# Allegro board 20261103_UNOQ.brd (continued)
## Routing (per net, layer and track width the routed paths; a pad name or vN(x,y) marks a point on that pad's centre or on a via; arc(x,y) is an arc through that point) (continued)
MCU_TRACE_CLK: length 43.6
  S6 w0.064: v1(17.91,9.15) 17.91,9.32 11.86,15.37 11.86,16.32 v5(12.59,17.05)
  G7 w0.064: v5(12.59,17.05) 12.7,17.16 12.7,19.38 14.9,21.58 v1(14.9,21.61)
  BOTTOM w0.066: JMISC1.4 43.81,11.48 41.65,9.31 18.07,9.31 v1(17.91,9.15)
MCU_TRACE_D0: length 69.3
  S6 w0.064: v5(4.67,20.7) 4.22,20.24 4.22,15.51 4.96,14.77 4.96,6.98 6.23,5.71 9.2,5.71 9.47,5.44 12.41,5.44 13.26,4.59 v5(14,4.59)
  G7 w0.064: v5(4.67,20.7) 5.08,20.7 5.21,20.57 6.5,20.57 7.06,20.02 8,20.02 8.26,20.27 9.96,20.27 10.59,20.9 12.47,20.9 13.15,21.58 v1(13.15,21.86) ; v1(20.37,9.57) 20.13,9.33 20.13,6.08 18.8,4.75 14.16,4.75 v5(14,4.59)
  BOTTOM w0.051: MCU1.D3 13.16,22.37 13.16,21.86
  BOTTOM w0.066: JMISC1.6 42.54,10.42 41.58,9.46 20.48,9.46 v1(20.37,9.57) ; 13.16,21.86 v1(13.15,21.86)
MCU_TRACE_D2: length 42.4
  S6 w0.064: v5(12.7,22.38) 12.7,17.47 11.71,16.48 11.71,15.32 17.57,9.46 v1(17.57,9.31)
  G7 w0.064: v1(13.39,22.2) 13.31,22.2 13.13,22.38 v5(12.7,22.38)
  BOTTOM w0.066: JMISC1.8 41.27,10.67 40.28,9.68 21.99,9.68 21.85,9.82 20.29,9.82 19.97,9.5 17.76,9.5 v1(17.57,9.31)
MCU_TRACE_D3: length 66.5
  S6 w0.064: v5(13.87,4.84) 13.23,4.84 12.45,5.62 9.49,5.62 9.26,5.85 6.29,5.85 5.1,7.04 5.1,14.85 4.37,15.58 4.37,19.91 4.95,20.5 4.95,21.56 v5(4.88,21.64)
  G7 w0.064: v1(19.98,9.91) 19.92,9.85 19.92,8.32 19.56,7.96 19.56,6.02 18.51,4.97 14,4.97 v5(13.87,4.84) ; v1(12.9,23.11) 12.69,23.32 12.35,23.32 12.14,23.11 12.14,22.02 11.66,21.54 11.02,21.54 10.9,21.41 8.56,21.41 8.1,20.95 5.36,20.95 4.88,21.44 v5(4.88,21.64)
  BOTTOM w0.066: v1(19.98,9.91) 20.05,9.98 38.69,9.98 40,11.29 40,11.98
MCU_USART1_RX: length 14.2
  S6 w0.064: v5(4.34,20.7) 4.62,20.98 4.62,23.24 4.57,23.29 v5(4.57,23.34)
  G7 w0.064: v1(12.4,23.61) 12.24,23.77 11.13,23.77 10.82,24.08 9.83,24.08 9.5,23.75 7.94,23.75 7.68,23.5 4.72,23.5 v5(4.57,23.34) ; v5(4.34,20.7) 4.62,20.42 6.3,20.42 6.99,19.74 v1(7.01,19.74)
MCU_USART1_RX_CONN: length 66.5
  S3 w0.064: v4(16.84,1.4) 16.84,1.3 17.22,0.92 21.24,0.92 24.02,3.7 24.02,5.76 24.46,6.2 31.27,6.2 32.56,4.9 48.15,4.9 49.6,6.35 50.6,6.35 50.8,6.15 JDIGITAL1.1
  S6 w0.064: v5(8.64,19.46) 8.64,19.09 6.92,17.38 6.92,13.05 6.76,12.88 6.76,10.79 8.9,8.65 11.44,8.65 17.3,2.79 17.3,1.85 v4(16.84,1.4)
  G7 w0.064: v1(7.39,19.23) 7.62,19.46 v5(8.64,19.46)
  BOTTOM w0.064: R2624.2 v1(7.39,19.23)
MCU_USART1_TX: length 3.5
  BOTTOM w0.051: MCU1.B5 14.64,23.37 15.44,23.37
  BOTTOM w0.064: 15.44,23.37 15.8,23.01 15.8,22.81 16.13,22.48 R2623.1
MCU_USART1_TX_CONN: length 62.7
  S3 w0.064: JDIGITAL1.2 49.78,6.6 49.55,6.6 48.03,5.08 32.64,5.08 31.34,6.38 24.39,6.38 23.84,5.83 23.84,3.78 21.16,1.1 17.86,1.1 17.64,1.32 v4(17.37,1.32)
  S6 w0.064: v4(17.37,1.32) 18.01,1.32 18.54,1.85 18.54,5.43 18.29,5.68 18.29,6.9 19.14,7.75 v5(19.14,8.92)
  G7 w0.064: v5(19.14,8.92) 19.14,10.51 18.83,10.82 18.83,12.78 18.49,13.12 18.49,13.79 19.53,14.83 v1(19.53,15.16)
  BOTTOM w0.064: R2623.2 18.31,22.48 19.3,21.49 19.3,15.49 19.53,15.27 v1(19.53,15.16)
MCU_VCAP: length 37
  V5 w0.203: v4(7.09,18.75) 7.39,18.75 8.2,19.56 8.2,25.84 v4(7.35,26.69)
  S6 w0.203: v4(7.35,26.69) 7.37,26.69 7.37,26.7 7.39,26.72 v1(7.62,26.72)
  S6 w0.254: v5(7.37,18.76) 7.1,18.76 v4(7.09,18.75)
  G7 w0.203: v1(19.25,14.99) 19.25,15.01 18.87,15.39 8.1,15.39 7.37,16.12 v5(7.37,18.76)
  BOTTOM w0.051: 8.11,26.61 MCU1.N11
  BOTTOM w0.2: MCU1.A4 15.11,23.11 16.15,22.07 C2501.1 16.31,21.84 16.51,21.64 18.14,21.64 18.92,20.85 18.92,15.37 19.23,15.07 19.23,14.99 v1(19.25,14.99)
  BOTTOM w0.203: v1(7.62,26.72) 8,26.72 8.11,26.61
MCU_VREF+: length 91.1
  V5 w0.524: v4(11.74,51.6) 10.71,52.63 7.93,52.63 7.11,51.81 7.11,50.61 4.8,48.3 4.8,32.79 7.7,29.89 7.7,27.96 6.46,26.72 6.44,26.72 5.58,25.86 5.58,22.23 7.14,20.68 v4(7.57,20.68)
  S6 w0.203: v5(7.87,20.68) v4(7.57,20.68)
  S6 w0.254: v4(11.74,51.6) v1(12.04,51.6)
  G7 w0.203: v1(8.48,20.6) 7.95,20.6 v5(7.87,20.68)
  BOTTOM w0.2: MCU1.L1 9.04,20.76 C2520.1 C2521.1 v1(8.48,20.6)
  BOTTOM w0.254: JDIGITAL1.16 48.44,44.7 48.11,44.37 46.6,44.37 C2614.1 44.39,43.96 44.06,43.63 U2501.3 41.26,43.11 40.57,42.42 34.98,42.42 34.14,41.58 20.22,41.58 18.5,43.3 18.5,47.13 14.39,51.24 12.4,51.24 v1(12.04,51.6)
MCU_VREF_EN: length 133.3
  TOP w0.066: v3(0.93,19.9) 1.04,19.79 1.04,4.45 1.78,3.71 3.62,3.71 v6(4.16,4.25)
  S3 w0.064: v3(0.93,19.9) v4(1.93,19.9)
  S6 w0.064: v5(3.4,19.65) 3.15,19.9 v4(1.93,19.9)
  G7 w0.064: v1(6.11,19.65) 5.9,19.86 3.61,19.86 v5(3.4,19.65) ; v1(48.98,3.82) 47.45,5.35 42.13,5.35 40.39,7.09 24.06,7.09 22.89,5.92 22.89,3.51 21.05,1.67 12.71,1.67 8.96,5.42 5.61,5.42 4.45,4.25 v6(4.16,4.25)
  BOTTOM w0.058: v1(6.11,19.65) 5.87,19.89 5.87,20.31 6.51,20.95 8.04,20.95 8.42,21.33 8.42,21.65 8.64,21.87 9.03,21.87
  BOTTOM w0.066: U2501.6 45.37,44.92 R2515.1 47.56,44.92 48.53,45.89 51.64,45.89 52.02,45.51 52.02,4.45 51.39,3.82 v1(48.98,3.82) ; 9.03,21.87 9.27,22.11 MCU1.M2
MIC2_BIAS: length 47.5
  S3 w0.127: v3(43.85,17.59) 43.6,17.35 42.5,17.35 42.41,17.44 40.71,17.44 v3(40.39,17.11)
  S3 w0.15: v4(20.66,4.35) 20.66,4.26 20.89,4.03 22.27,4.03 22.49,4.26 22.49,6.49 23.7,7.7 45.85,7.7 47.22,9.07 47.22,9.08 47.38,9.24 47.39,9.24 48.13,9.98 48.13,16.71 47.01,17.83 44.08,17.83 v3(43.85,17.59)
  S6 w0.15: v4(20.66,4.35) 20.62,4.31 v1(19.94,4.31)
MIC2_BIAS_CONN: length 6.5
  BOTTOM w0.15: JMISC1.33 24.76,7.55 23.19,5.98 22.14,5.98 21.6,5.44 21.04,5.44 20.61,5.01 D26067.2 20.61,4.88 20.61,4.48 R2646.1
MIC2_INN: length 46.1
  S3 w0.127: v3(39.82,15.98) 41.1,17.26 41.72,17.26 42.21,16.76 42.62,16.76 42.7,16.84 43.6,16.84 v3(43.82,17.06)
  S3 w0.15: v4(21.35,4.41) 21.44,4.32 22.07,4.32 22.24,4.49 22.24,6.59 23.67,8.03 45.62,8.03 47.83,10.24 47.83,16.37 46.83,17.37 44.13,17.37 v3(43.82,17.06)
  S6 w0.15: v1(21.02,4.37) 21.31,4.37 v4(21.35,4.41)
MIC2_INN_CONN: length 6.7
  BOTTOM w0.15: R2637.1 21.5,4.39 D26066.2 22.31,5.72 23.3,5.72 24.62,7.04 25.56,7.04 26.05,7.53 26.05,8.07 JMISC1.31
MIC2_INP: length 44.9
  S3 w0.127: v3(43.82,16.53) 43.52,16.23 42.58,16.23 42.48,16.33 41.25,16.33 40.92,16 40.46,16 40.16,15.7 v3(39.54,15.7)
  S3 w0.15: v4(21.87,4.66) 21.95,4.74 21.95,6.64 23.67,8.36 45.42,8.36 47.57,10.52 47.57,16.27 46.76,17.08 44.37,17.08 v3(43.82,16.53)
  S6 w0.15: v1(22.58,4.37) 22.16,4.37 v4(21.87,4.66)
MIC2_INP_CONN: length 7.5
  BOTTOM w0.15: JMISC1.29 27.32,8.07 27.32,7.64 26.41,6.73 24.71,6.73 23.42,5.44 22.39,5.44 22.09,5.14 D26065.2 22.09,4.38 R2636.1
MIPI_DSI0_CLK_M: length 68.9
  TOP w0.058: U3001.H8 37.53,51.3 37.76,51.3 38.06,51 38.06,50.81 38.3,50.57 38.54,50.57 v3(38.73,50.37)
  S3 w0.051: 29.6,28.33 29.6,28.35 29.59,28.35 29.59,28.48 29.97,28.85 29.97,29.49 v3(30.17,29.68)
  S3 w0.053: 29.6,28.33 29.6,28.14 27.01,25.55 23.25,25.55 21.79,24.09 19.29,24.09 19.16,24.22 18.94,24.22 v4(18.77,24.05) ; v3(38.73,50.37) 38.93,50.56 39.05,50.56 39.25,50.36 39.25,48.85 39.38,48.72 39.38,48.29 v4(39.2,48.11)
  S6 w0.053: v4(39.2,48.11) 39.38,47.93 39.38,45.74 36.27,42.64 34.34,42.64 33.17,41.47 19.5,41.47 18.14,40.1 18.14,32.11 18.26,31.99 19.11,31.99 19.16,31.93 19.16,31.73 19.11,31.68 18.26,31.68 18.14,31.56 18.14,31.19 18.26,31.07 19.1,31.07 19.15,31.02 19.15,30.82 19.1,30.76 18.26,30.76 18.14,30.64 18.14,30.35 18.26,30.22 19.1,30.22 19.15,30.17 19.15,29.97 19.1,29.92 18.26,29.92 18.14,29.8 18.14,29.5 18.26,29.38 18.57,29.38 18.62,29.32 18.62,29.12 18.57,29.07 18.26,29.07 18.14,28.95 18.14,28.65 18.26,28.53 18.57,28.53 18.62,28.47 18.62,28.27 18.57,28.22 18.26,28.22 18.14,28.1 18.14,24.42 18.32,24.24 18.58,24.24 v4(18.77,24.05)
MIPI_DSI0_CLK_M_CONN: length 22
  TOP w0.058: 39.24,50.37 39.44,50.57 40.2,50.57 40.61,50.98 40.94,50.98 41.08,51.12 41.08,51.53 41.14,51.59 41.26,51.59 41.32,51.53 41.32,51.12 41.45,50.98 41.98,50.98 42.13,51.13 42.13,51.5 v3(42.22,51.59)
  S3 w0.053: v4(42.99,53.57) 43.18,53.76 43.18,54.04 43.38,54.24 44.18,54.24 44.5,53.92 44.5,52.61 44.18,52.29 43.53,52.29 43.48,52.24 43.48,52.05 43.36,51.93 43.15,51.93 43.03,52.05 43.03,52.24 42.98,52.29 42.29,52.29 42.11,52.11 42.11,51.7 v3(42.22,51.59)
  S6 w0.053: v4(42.99,53.57) 43.04,53.52 v1(43.04,53.29)
  BOTTOM w0.058: v1(43.04,53.29) 43.14,53.19 43.14,52.91 43.08,52.85 43.07,52.85 43.01,52.79 43.01,52.67 43.07,52.61 43.08,52.61 43.14,52.56 43.14,52.3 43.3,52.15 44.04,52.15 44.16,52.03 44.16,51.59 43.96,51.39 42.18,51.39 42.12,51.45 42.12,51.73 42.3,51.91 U2612.1 U2612.10 42.3,53.24 42.12,53.42 42.12,53.57 42.32,53.77 43.02,53.77 43.25,54 43.25,54.89 43.31,54.95 JMEDIA1.3
MIPI_DSI0_CLK_P: length 68.9
  TOP w0.058: v3(38.73,50.91) 38.54,50.71 38.35,50.71 38.19,50.87 38.19,51.06 37.82,51.43 37.49,51.43 U3001.G8
  S3 w0.051: 29.48,28.33 29.48,28.35 29.48,28.35 29.48,28.52 29.86,28.9 29.86,29.21 29.79,29.28 v3(29.77,29.28)
  S3 w0.053: 29.48,28.33 29.48,28.18 26.96,25.67 23.2,25.67 21.74,24.21 20.87,24.21 20.81,24.26 20.81,24.32 20.76,24.37 20.65,24.37 20.6,24.32 20.6,24.26 20.55,24.21 20.44,24.21 20.39,24.26 20.39,24.32 20.33,24.37 20.23,24.37 20.18,24.32 20.18,24.26 20.12,24.21 20.02,24.21 19.96,24.26 19.96,24.32 19.91,24.37 19.8,24.37 19.75,24.32 19.75,24.26 19.7,24.21 19.34,24.21 19.21,24.34 18.96,24.34 v4(18.77,24.53) ; v4(39.68,48.11) 39.5,48.29 39.5,48.77 39.37,48.9 39.37,50.41 39.1,50.68 38.95,50.68 38.73,50.9 v3(38.73,50.91)
  S6 w0.053: v4(18.77,24.53) 18.6,24.36 18.37,24.36 18.25,24.47 18.25,28.05 18.31,28.1 18.62,28.1 18.74,28.23 18.74,28.52 18.62,28.64 18.31,28.64 18.25,28.7 18.25,28.9 18.31,28.95 18.62,28.95 18.74,29.07 18.74,29.37 18.62,29.49 18.31,29.49 18.25,29.55 18.25,29.75 18.31,29.8 19.15,29.8 19.27,29.92 19.27,30.22 19.15,30.34 18.31,30.34 18.25,30.39 18.25,30.59 18.31,30.65 19.15,30.65 19.27,30.77 19.27,31.07 19.15,31.19 18.31,31.19 18.25,31.24 18.25,31.51 18.31,31.56 19.16,31.56 19.28,31.68 19.28,31.98 19.16,32.1 18.31,32.1 18.25,32.16 18.25,40.05 19.55,41.35 33.22,41.35 34.39,42.52 36.32,42.52 39.5,45.69 39.5,47.93 v4(39.68,48.11)
MIPI_DSI0_CLK_P_CONN: length 22
  TOP w0.058: 39.24,50.91 39.24,50.83 39.36,50.71 39.57,50.71 39.63,50.77 39.63,50.82 39.69,50.88 39.8,50.88 39.86,50.82 39.86,50.77 39.92,50.71 40.15,50.71 40.55,51.11 40.89,51.11 40.95,51.17 40.95,51.58 41.08,51.72 41.31,51.72 41.45,51.58 41.45,51.17 41.51,51.11 41.92,51.11 42,51.19 42,51.48 v3(41.89,51.59)
  S3 w0.053: v4(43.47,53.57) 43.3,53.74 43.3,53.99 43.43,54.12 44.13,54.12 44.38,53.87 44.38,52.66 44.13,52.41 43.48,52.41 43.36,52.29 43.36,52.1 43.31,52.05 43.2,52.05 43.15,52.1 43.15,52.29 43.03,52.41 42.25,52.41 42,52.16 42,51.7 v3(41.89,51.59)
  S6 w0.053: v4(43.47,53.57) 43.37,53.47 v1(43.37,53.29)
  BOTTOM w0.058: JMEDIA1.5 43.05,54.95 43.11,54.89 43.11,54.05 42.96,53.9 42.26,53.9 41.99,53.63 41.99,53.42 41.8,53.23 U2612.9 U2612.2 41.8,51.91 41.98,51.73 41.98,51.39 42.12,51.26 44.02,51.26 44.29,51.53 44.29,52.09 44.1,52.28 43.35,52.28 43.27,52.36 43.27,53.19 v1(43.37,53.29)
MIPI_DSI0_L0_M: length 68.9
  TOP w0.058: 30.17,28.48 v3(30.12,28.35) ; U3001.F8 37.51,52.08 37.9,52.08 38.07,51.91 38.49,51.91 v3(38.71,51.69)
  S3 w0.053: v3(30.12,28.35) 30.04,28.35 30.02,28.33 30.02,28.03 27.24,25.25 23.5,25.25 21.39,23.14 19.53,23.14 v4(19.33,22.94) ; v4(39.94,49.68) 40.12,49.86 40.12,50.91 39.15,51.88 38.9,51.88 v3(38.71,51.69)
  S6 w0.053: v4(19.33,22.94) 19.15,23.11 18.84,23.11 17.63,24.32 17.63,40.27 19.26,41.9 32.95,41.9 34.19,43.14 36.1,43.14 38.69,45.74 38.69,48.46 38.94,48.71 39.89,48.71 40.28,48.32 40.28,47.04 40.33,46.98 40.59,46.98 40.66,47.06 40.66,48.71 40.12,49.25 40.12,49.5 v4(39.94,49.68)
MIPI_DSI0_L0_M_CONN: length 22
  TOP w0.058: R1503.2 39.42,51.89 39.75,51.89 39.99,51.65 40.23,51.65 40.34,51.54 v3(40.35,51.54)
  S3 w0.053: v3(40.35,51.54) 40.47,51.66 40.89,51.66 41.41,51.14 41.41,50.58 41.32,50.49 41.11,50.49 v4(40.92,50.68)
  S6 w0.053: v1(40.65,50.61) 40.85,50.61 v4(40.92,50.68) ; v1(42.3,50.7) 42.49,50.51 42.86,50.51 43.19,50.84 43.19,51.34 43.14,51.39 43.05,51.39 42.99,51.44 42.99,51.55 43.05,51.6 43.14,51.6 43.19,51.66 43.19,51.76 43.14,51.82 43.05,51.82 42.99,51.87 42.99,51.98 43.05,52.03 43.14,52.03 43.19,52.08 43.19,52.39 44.24,53.44 44.24,55.53 44.11,55.66 43.69,55.66 43.64,55.61 43.64,55.4 43.52,55.28 43.32,55.28 43.19,55.4 43.19,55.61 43.14,55.66 43.03,55.66 42.98,55.61 42.98,55.4 42.86,55.28 42.66,55.28 42.53,55.4 42.53,55.61 42.48,55.66 41.76,55.66 41.6,55.82 41.6,56.07 v1(41.48,56.19)
  BOTTOM w0.058: v1(41.48,56.19) 41.59,56.29 41.59,56.77 41.19,57.17 39.79,57.17 39.3,57.66 39.3,58.79 39.24,58.85 JMEDIA1.12 ; v1(40.65,50.61) 40.74,50.52 40.98,50.52 41.16,50.7 U2611.10 v1(42.3,50.7)
MIPI_DSI0_L0_P: length 68.8
  TOP w0.058: SOC1.R30 v3(29.82,28.35) ; U3001.E8 37.51,52.21 37.96,52.21 38.13,52.04 38.53,52.04 v3(38.71,52.22)
  S3 w0.053: v4(19.33,23.41) 19.49,23.26 19.76,23.26 19.81,23.31 19.81,23.37 19.87,23.42 19.97,23.42 20.03,23.37 20.03,23.31 20.08,23.26 21.34,23.26 23.45,25.37 27.2,25.37 29.91,28.08 29.91,28.33 29.89,28.35 v3(29.82,28.35) ; v4(40.41,49.68) 40.23,49.86 40.23,50.95 39.19,51.99 38.94,51.99 v3(38.71,52.22)
  S6 w0.053: v4(19.33,23.41) 19.15,23.23 18.88,23.23 17.74,24.37 17.74,40.22 19.3,41.78 32.99,41.78 34.24,43.03 36.14,43.03 38.81,45.69 38.81,48.41 38.99,48.59 39.84,48.59 40.16,48.27 40.16,46.99 40.28,46.87 40.64,46.87 40.78,47.01 40.78,48.76 40.23,49.3 40.23,49.5 v4(40.41,49.68)
MIPI_DSI0_L0_P_CONN: length 22
  TOP w0.058: R1504.2 39.42,52.02 39.81,52.02 40.05,51.78 40.26,51.78 v3(40.35,51.87)
  S3 w0.053: v4(40.92,50.2) 41.09,50.37 41.37,50.37 41.53,50.53 41.53,51.19 40.94,51.78 40.44,51.78 v3(40.35,51.87)
  S6 w0.053: v1(41.81,56.19) 41.72,56.09 41.72,55.87 41.81,55.78 42.53,55.78 42.65,55.66 42.65,55.45 42.7,55.4 42.81,55.4 42.86,55.45 42.86,55.66 42.99,55.78 43.19,55.78 43.31,55.66 43.31,55.45 43.36,55.4 43.47,55.4 43.52,55.45 43.52,55.66 43.65,55.78 44.16,55.78 44.36,55.58 44.36,53.39 43.31,52.34 43.31,50.79 42.91,50.39 42.49,50.39 v1(42.3,50.2) ; v4(40.92,50.2) 40.84,50.28 v1(40.65,50.28)
  BOTTOM w0.058: v1(40.65,50.28) 40.75,50.38 40.98,50.38 41.16,50.2 U2611.9 v1(42.3,50.2) ; v1(41.81,56.19) 41.72,56.27 41.72,56.83 41.25,57.3 39.85,57.3 39.44,57.71 39.44,58.79 39.5,58.85 JMEDIA1.10
MIPI_DSI0_L1_M: length 68.8
  TOP w0.058: v3(36.91,49.68) 37.1,49.88 37.1,50.24 36.71,50.63 36.71,51.01 U3001.H6
  S3 w0.05: 31.16,28.33 31.16,28.35 v3(31.04,28.47)
  S3 w0.053: v3(36.91,49.68) 36.91,49.46 v4(36.96,49.4) ; 31.16,28.33 31.16,27.8 27.77,24.42 24.47,24.42 20.75,20.7 20.68,20.7 20.67,20.71 20.59,20.71 20.52,20.64 20.52,20.56 20.53,20.55 20.53,20.47 20.45,20.4 20.37,20.4 20.36,20.41 20.29,20.41 20.21,20.33 20.21,20.26 20.22,20.25 20.22,20.17 20.09,20.04 19.74,20.04 19.69,20.09 19.69,20.15 19.63,20.2 19.53,20.2 19.47,20.15 19.47,20.09 19.42,20.04 19.2,20.04 v4(19.02,20.21)
  S6 w0.053: v4(19.02,20.21) 18.83,20.02 18.65,20.02 18.47,20.2 18.47,22.6 16.86,24.21 16.86,40.43 18.98,42.56 32.55,42.56 33.98,43.99 35.76,43.99 37.03,45.26 37.03,48.02 38.07,49.06 38.07,49.69 37.83,49.93 37.26,49.93 37.12,49.79 37.12,49.56 v4(36.96,49.4)
MIPI_DSI0_L1_M_CONN: length 22.3
  TOP w0.058: v3(40.12,48.52) 40.23,48.62 40.23,48.82 40.09,48.96 39.48,48.96 38.8,48.28 37.32,48.28 37.11,48.49 37.11,48.98 R1505.2
  S3 w0.053: v4(41.36,49.18) 41.19,49.01 40.41,49.01 40.23,48.83 40.23,48.63 v3(40.12,48.52)
  S6 w0.053: v1(41.64,49.2) 41.62,49.18 v4(41.36,49.18)
  BOTTOM w0.058: U2611.7 v1(41.64,49.2) U2611.4 42.53,49.2 42.71,49.02 43.13,49.02 44.86,50.75 44.86,51.88 46.24,53.26 46.24,56.34 44.99,57.59 43.37,57.59 43.11,57.85 43.11,58.79 43.05,58.85 JMEDIA1.6
MIPI_DSI0_L1_P: length 68.8
  TOP w0.058: v3(37.44,49.68) 37.24,49.89 37.24,50.29 36.84,50.69 36.84,51.01 U3001.H7
  S3 w0.05: v3(31.04,28.87) 31.16,28.75 31.16,28.74 31.27,28.64 31.27,28.35 31.27,28.35 31.27,28.33
  S3 w0.053: 31.27,28.33 31.27,27.75 27.82,24.3 24.52,24.3 20.14,19.92 19.21,19.92 v4(19.02,19.74) ; v4(37.44,49.4) v3(37.44,49.68)
  S6 w0.053: v4(37.44,49.4) 37.23,49.61 37.23,49.74 37.31,49.81 37.78,49.81 37.96,49.64 37.96,49.11 36.92,48.07 36.92,45.31 35.71,44.11 33.93,44.11 32.5,42.67 18.93,42.67 16.74,40.48 16.74,24.16 18.35,22.55 18.35,20.15 18.6,19.9 18.81,19.9 18.97,19.74 v4(19.02,19.74)
MIPI_DSI0_L1_P_CONN: length 22.3
  TOP w0.058: R1506.2 37.24,48.98 37.24,48.55 37.38,48.41 38.74,48.41 39.42,49.09 40.15,49.09 40.36,48.88 40.36,48.61 v3(40.45,48.52)
  S3 w0.053: v3(40.45,48.52) 40.34,48.63 40.34,48.78 40.46,48.89 41.17,48.89 v4(41.36,48.7)
  S6 w0.053: v4(41.36,48.7) v1(41.64,48.7)
  BOTTOM w0.058: U2611.6 v1(41.64,48.7) U2611.5 42.54,48.7 42.72,48.88 43.18,48.88 44.99,50.69 44.99,51.82 46.37,53.2 46.37,56.4 45.05,57.72 43.43,57.72 43.25,57.9 43.25,58.79 43.31,58.85 JMEDIA1.4
MIPI_DSI0_L2_M: length 68.9
  TOP w0.058: v3(38.71,52.93) 38.51,53.13 38.33,53.13 38.07,52.88 37.51,52.88 U3001.D8
  S3 w0.053: v4(19.22,21.66) 19.41,21.84 20.4,21.84 20.93,22.37 21.2,22.37 23.78,24.95 27.48,24.95 30.43,27.9 30.43,28.74 v3(30.57,28.88) ; v3(38.71,52.93) 38.74,52.96 v4(39.01,52.96)
  S6 w0.053: v4(19.22,21.66) 18.98,21.9 18.8,21.9 18.68,22.03 18.68,22.79 17.18,24.29 17.18,40.4 19.09,42.31 32.65,42.31 33.98,43.64 36,43.64 38.21,45.84 38.21,48.59 38.5,48.88 38.5,50.28 39.22,51 39.4,51 39.52,50.87 39.6,50.87 39.67,50.95 39.67,51.02 39.55,51.15 39.55,51.32 39.8,51.58 39.8,52.9 39.55,53.15 39.2,53.15 v4(39.01,52.96)
MIPI_DSI0_L2_M_CONN: length 22.3
  TOP w0.058: R1507.2 39.4,53.12 39.5,53.12 v3(39.6,53.02)
  S3 w0.053: v3(39.6,53.02) 39.71,53.13 40,53.13 40.14,53.27 40.14,53.55 40.19,53.6 40.24,53.6 40.29,53.65 40.29,53.76 40.24,53.81 40.19,53.81 40.14,53.86 40.14,54.99 40.02,55.12 39.01,55.12 38.96,55.17 38.96,55.28 39.01,55.33 40.02,55.33 40.14,55.45 40.14,55.65 40.02,55.78 39.01,55.78 38.96,55.83 38.96,55.94 39.01,55.99 40.02,55.99 40.14,56.11 40.14,56.84 40.26,56.96 40.63,56.96 40.74,56.85 40.74,55.05 40.99,54.8 41.24,54.8 v4(41.41,54.63)
  S6 w0.053: v4(41.41,54.63) 41.23,54.81 40.66,54.81 40.53,54.68 40.53,53.9 40.58,53.85 41.29,53.85 41.41,53.72 41.41,53.52 41.29,53.4 40.58,53.4 40.53,53.35 40.53,52.46 40.6,52.39 40.6,52.16 v1(40.71,52.05)
  BOTTOM w0.058: v1(40.71,52.05) U2612.4 U2612.7 40.62,53.2 40.62,53.6 40.42,53.8 39.68,53.8 39.44,54.04 39.44,54.89 39.5,54.95 JMEDIA1.9
MIPI_DSI0_L2_P: length 68.9
  TOP w0.058: v3(38.71,53.44) 38.53,53.26 38.27,53.26 38.02,53.01 37.51,53.01 U3001.C8
  S3 w0.053: v4(39.01,53.44) v3(38.71,53.44) ; v3(30.17,28.88) 30.31,28.74 30.31,27.95 27.43,25.07 23.73,25.07 21.16,22.49 20.88,22.49 20.35,21.96 20.02,21.96 19.97,22.01 19.97,22.11 19.92,22.16 19.81,22.16 19.76,22.11 19.76,22.01 19.7,21.96 19.4,21.96 v4(19.22,22.14)
  S6 w0.053: v4(39.01,53.44) 39.19,53.26 39.6,53.26 39.92,52.95 39.92,51.53 39.66,51.27 39.66,51.2 39.79,51.07 39.79,50.9 39.65,50.76 39.47,50.76 39.35,50.88 39.27,50.88 38.62,50.23 38.62,48.83 38.33,48.54 38.33,45.8 36.05,43.52 34.03,43.52 32.7,42.19 19.13,42.19 17.3,40.35 17.3,24.34 18.8,22.84 18.8,22.07 18.85,22.02 19.11,22.02 v4(19.22,22.14)
MIPI_DSI0_L2_P_CONN: length 22.3
  TOP w0.058: v3(39.6,53.35) 39.5,53.25 39.4,53.25 R1508.2
  S3 w0.053: v4(41.41,55.11) 41.22,54.92 41.04,54.92 40.86,55.1 40.86,56.9 40.68,57.08 40.21,57.08 40.02,56.89 40.02,56.16 39.97,56.11 38.96,56.11 38.84,55.98 38.84,55.78 38.96,55.66 39.97,55.66 40.02,55.61 40.02,55.5 39.97,55.45 38.96,55.45 38.84,55.32 38.84,55.12 38.96,55 39.97,55 40.02,54.95 40.02,53.32 39.95,53.24 39.71,53.24 v3(39.6,53.35)
  S6 w0.053: v4(41.41,55.11) 41.23,54.93 40.61,54.93 40.41,54.73 40.41,53.85 40.53,53.73 41.24,53.73 41.3,53.68 41.3,53.57 41.24,53.52 40.53,53.52 40.41,53.39 40.41,52.41 40.48,52.34 40.48,52.15 v1(40.38,52.05)
  BOTTOM w0.058: v1(40.38,52.05) 40.3,52.13 U2612.5 U2612.6 40.49,53.2 40.49,53.54 40.36,53.67 39.62,53.67 39.3,53.99 39.3,54.89 39.24,54.95 JMEDIA1.11
MIPI_DSI0_L3_M: length 68.9
  TOP w0.058: U3001.H4 35.91,51.01 35.91,49.88 v3(35.71,49.68)
  S3 w0.05: 30.64,28.33 30.64,28.39 30.65,28.4 ; v3(30.57,29.28) 30.64,29.21
  S3 w0.053: 30.64,29.21 30.64,29.06 30.74,28.96 30.74,28.81 30.65,28.71 30.65,28.4 ; v3(35.71,49.68) 35.71,49.43 v4(35.74,49.4) ; v4(17.83,21.44) 17.83,21.21 17.93,21.11 18.12,21.11 18.18,21.16 18.18,21.21 18.23,21.26 18.34,21.26 18.39,21.21 18.39,21.16 18.44,21.11 18.55,21.11 18.6,21.16 18.6,21.21 18.66,21.26 18.76,21.26 18.82,21.21 18.82,21.16 18.87,21.11 18.98,21.11 19.03,21.16 19.03,21.21 19.08,21.26 19.19,21.26 19.24,21.21 19.24,21.16 19.3,21.11 19.4,21.11 19.46,21.16 19.46,21.21 19.51,21.26 19.62,21.26 19.67,21.21 19.67,21.16 19.72,21.11 19.83,21.11 19.88,21.16 19.88,21.21 19.94,21.26 20.04,21.26 20.1,21.21 20.1,21.16 20.15,21.11 20.37,21.11 20.5,21.24 20.5,21.32 20.48,21.34 20.48,21.41 20.56,21.49 20.63,21.49 20.66,21.47 20.73,21.47 20.81,21.54 20.81,21.62 20.78,21.64 20.78,21.71 20.86,21.79 20.94,21.79 20.96,21.77 21.03,21.77 24.03,24.77 27.65,24.77 30.64,27.76 30.64,28.33
  S6 w0.053: v4(35.74,49.4) 35.92,49.58 35.92,49.67 35.87,49.72 35.42,49.72 35.23,49.53 35.23,49.18 35.85,48.55 35.85,48.38 35.72,48.25 35.72,48.17 35.8,48.1 35.87,48.1 36,48.23 36.18,48.23 36.63,47.78 36.63,45.57 35.59,44.53 33.94,44.53 32.38,42.96 18.81,42.96 16.45,40.6 16.45,23.8 17.42,22.82 17.42,21.59 17.58,21.44 v4(17.83,21.44)
MIPI_DSI0_L3_M_CONN: length 22.2
  TOP w0.058: R1509.2 35.9,48.99 35.9,48.71 35.84,48.65 35.66,48.65 35.6,48.59 35.6,48.47 35.66,48.41 35.84,48.41 35.9,48.36 35.9,47.91 35.19,47.2 31.42,47.2 31.33,47.29 31.33,47.61 31.43,47.71 34.4,47.71 34.61,47.92 34.61,48.37 34.41,48.57 33.55,48.57 v3(33.44,48.68)
  S3 w0.053: v4(33.15,48.77) 33.24,48.68 v3(33.44,48.68)
  S6 w0.053: v1(32.87,48.69) 33.07,48.69 v4(33.15,48.77)
  BOTTOM w0.058: JMEDIA1.15 35.69,54.95 35.63,54.89 35.63,53.88 35.49,53.74 34.56,53.74 34.44,53.62 34.44,53.31 U2606.10 U2606.1 34.63,52.01 34.45,51.83 34.45,51.6 32.41,49.57 32.41,48.67 32.48,48.6 32.78,48.6 v1(32.87,48.69)
MIPI_DSI0_L3_P: length 68.9
  TOP w0.058: U3001.H5 36.04,51.01 36.04,49.86 v3(36.22,49.68)
  S3 w0.05: 30.76,28.4 30.76,28.38 30.76,28.38 30.76,28.35 30.76,28.34 30.76,28.33 ; 30.76,29.21 30.76,29.22 30.76,29.22 30.76,29.25 ; 30.76,29.49 v3(30.57,29.68)
  S3 w0.053: 30.76,29.25 30.76,29.49 ; v4(36.22,49.4) v3(36.22,49.68) ; v4(17.49,21.1) 17.77,21.1 17.88,20.99 20.42,20.99 24.08,24.65 27.7,24.65 30.76,27.71 30.76,28.33 ; 30.76,28.4 30.76,28.66 30.86,28.76 30.86,29 30.76,29.1 30.76,29.21
  S6 w0.053: v4(36.22,49.4) 36.04,49.58 36.04,49.72 35.92,49.84 35.37,49.84 35.11,49.58 35.11,49.13 35.74,48.5 35.74,48.43 35.61,48.3 35.61,48.12 35.75,47.98 35.92,47.98 36.05,48.11 36.13,48.11 36.51,47.73 36.51,45.62 35.54,44.64 33.89,44.64 32.33,43.08 18.77,43.08 16.33,40.65 16.33,23.75 17.31,22.77 17.31,21.54 17.49,21.36 v4(17.49,21.1)
MIPI_DSI0_L3_P_CONN: length 22.1
  TOP w0.058: v3(33.44,48.35) 33.53,48.44 34.35,48.44 34.48,48.31 34.48,47.98 34.34,47.84 31.37,47.84 31.2,47.67 31.2,47.23 31.36,47.07 35.25,47.07 36.03,47.85 36.03,48.99 R1510.2
  S3 w0.053: v3(33.44,48.35) 33.21,48.35 v4(33.15,48.29)
  S6 w0.053: v4(33.15,48.29) 33.08,48.36 v1(32.87,48.36)
  BOTTOM w0.058: 34.92,54.95 35.43,54.95 35.49,54.89 35.49,53.93 35.43,53.87 34.5,53.87 34.31,53.68 34.31,53.29 U2606.9 U2606.2 34.13,52.01 34.31,51.83 34.31,51.66 32.28,49.62 32.28,48.61 32.42,48.47 32.76,48.47 v1(32.87,48.36)
MUX_ALERT: length 51
  TOP w0.066: U3001.B8 37.54,53.54 v3(37.64,53.44) 38.25,54.05 R3025.2 ; v3(25.32,28.55) 24.99,28.88 SOC1.AG29
  S3 w0.064: v4(39.41,43.62) 39.41,46.13 38.5,47.04 38.5,50 38.28,50.22 38.28,51.88 37.64,52.52 v3(37.64,53.44) ; v3(25.32,28.55) 25.03,28.26 20.22,28.26 20.17,28.21 v4(19.53,28.21)
  S6 w0.064: v4(39.41,43.62) 38.72,42.94 37.34,42.94 36.52,42.11 34.51,42.11 33.19,40.79 22.12,40.79 19.5,38.17 19.5,37.13 19.86,36.77 19.86,28.91 19.53,28.57 v4(19.53,28.21)
MUX_CABLE_DET: length 42.3
  TOP w0.066: v3(14.89,49.25) 22.01,49.25 v3(22.55,49.79) ; v3(33.83,51.66) 33.43,52.07 TP3007.1 ; SOC1.AG1 v3(24.54,40.51)
  S3 w0.064: v3(35.37,53.14) 35.37,53.1 35.15,52.88 34.52,52.88 34.44,52.81 34.44,52.27 v3(33.83,51.66) 33.71,51.54 33.71,51.05 34.37,50.39 34.37,50.08 34.21,49.92 32.96,49.92 32.17,50.71 30.7,50.71 30.5,50.91 v4(30.09,50.91) ; v3(22.55,49.79) 22.55,50.14 v4(22.47,50.22) ; v3(24.54,40.51) 24.43,40.61 22.56,40.61 20.47,42.7 18.59,42.7 15.83,45.46 15.83,48.37 14.95,49.25 v3(14.89,49.25)
  S6 w0.064: v4(30.09,50.91) 29.93,51.07 26.52,51.07 26.34,50.89 26.34,50.3 26.26,50.22 v4(22.47,50.22)
MUX_DP_HPD: length 4.9
  TOP w0.066: SOC1.K1 31.77,41.45 32.18,41.86 34.99,41.86 R3028.2
MUX_DP_HPD_R: length 15.5
  TOP w0.066: v3(39.25,41.73) 39.1,41.88 35.77,41.88 R3028.1
  S3 w0.064: v3(39.25,41.73) 39.03,41.95 38.71,41.95 38.51,42.15 38.51,46.21 37.97,46.75 37.97,49.86 37.82,50.01 37.82,51.52 37.02,52.32 v3(36.98,52.32)
MUX_I2C_SCL_R: length 14
  TOP w0.066: R3014.2 35.51,43.78 TP3002.1 35.89,43.82 36.17,44.1 37.97,44.1 38.35,43.72 v3(38.8,43.72)
  S3 w0.064: v3(38.8,43.72) 38.8,46.23 38.15,46.88 38.15,49.9 37.97,50.08 37.97,51.63 37.02,52.58 37.02,52.74 v3(36.98,52.78)
MUX_I2C_SDA_R: length 19.2
  TOP w0.066: R3015.2 30.99,44.43 TP3003.1 31.35,44.79 37.53,44.79 38.39,43.93 v3(39.01,43.93)
  S3 w0.064: v3(37.01,53.11) 37.2,52.92 37.2,52.69 38.13,51.76 38.13,50.13 38.32,49.94 38.32,46.96 38.98,46.3 38.98,44.51 39.01,44.48 v3(39.01,43.93)
MUX_LDO_EN: length 1.1
  TOP w0.066: 25.7,60.83 25.7,60.82 U3004.3
MUX_POWER_EN: length 55.1
  TOP w0.066: SOC1.AE1 25.77,40.45 25.58,40.64 v3(25.5,40.64)
  G2 w0.191: v3(34.77,52.58) 34.8,52.58 v2(34.95,52.73)
  S3 w0.064: v4(35.05,52.53) 34.98,52.53 34.92,52.58 v3(34.77,52.58) ; v4(15.03,51.54) 14.37,50.88 14.37,50.16 16.03,48.5 16.03,45.49 18.64,42.88 20.56,42.88 22.68,40.76 25.39,40.76 v3(25.5,40.64)
  S6 w0.064: v1(15.3,51.42) 15.15,51.42 v4(15.03,51.54) ; v1(35.26,52.73) v4(35.05,52.53)
  BOTTOM w0.066: TP3001.1 16.01,50.74 15.99,50.74 ; 15.99,50.74 19.37,47.36 19.37,43.43 20.43,42.36 30.3,42.36 32.76,44.82 32.76,47.47 33.44,48.15 33.44,49.98 35.59,52.13 R3022.2 35.59,52.68 C3028.1 35.43,52.91 v1(35.26,52.73) ; 15.99,50.74 v1(15.3,51.42)
MUX_RESET_N: length 43.1
  TOP w0.066: v3(38.71,54.43) R3023.2 38.53,54.79 TP3006.1 38.68,55.32 C3027.1
  S3 w0.064: 37.97,53.49 37.97,52.49 38.43,52.02 38.43,50.28 38.66,50.06 38.66,47.2 v4(40.08,45.78) ; 37.97,53.49 37.97,53.71 38.08,53.82 38.38,53.82 38.71,54.15 v3(38.71,54.43) ; 37.97,53.49 37.8,53.66 37.09,53.66 v3(37.02,53.59) ; v4(19.24,38.33) 19.77,38.33 19.92,38.48 v3(25.37,38.48)
  S6 w0.064: v4(19.24,38.33) 19.46,38.33 22.15,41.02 33.22,41.02 34.49,42.29 36.5,42.29 39.99,45.78 v4(40.08,45.78)
MUX_SBU1: length 4.9
  TOP w0.051: v3(35.73,59.77) U2602.1 35.73,58.61 35.88,58.46 35.88,58.19 C3019.2 34.93,58.01 R3003.2
  S3 w0.048: v3(35.73,59.77) 35.9,59.94 35.9,60.26 36.18,60.53 36.59,60.53 37.03,60.98 37.03,61.17 v3(36.97,61.23)
MUX_SBU2: length 8.2
  TOP w0.051: R3004.2 C3020.2 36.06,58.19 36.06,58.45 36.23,58.62 U2602.2 v3(36.23,59.77)
  S3 w0.048: v3(38.72,62.53) 38.33,62.92 37.27,62.92 36.97,62.62 36.97,61.59 37.19,61.37 37.19,60.91 36.66,60.38 36.25,60.38 36.06,60.19 36.06,59.94 v3(36.23,59.77)
MUX_SSRXN1: length 20.1
  TOP w0.053: C2629.2 R2665.1 44.21,61.11 43.92,60.82 43.92,59.82 44.08,59.66 44.08,58.87 v3(44.2,58.75)
  S3 w0.051: v3(44.2,58.75) 44.26,58.81 v4(44.26,59.03) ; v3(35.37,53.54) 35.51,53.68 35.51,53.87 35.13,54.25 35.13,55.38 35.08,55.43 34.97,55.43 34.92,55.48 34.92,55.58 34.97,55.63 35.08,55.63 35.13,55.68 35.13,55.86 v4(34.95,56.03)
  S6 w0.051: v4(34.95,56.03) 35.13,56.21 35.13,56.54 35.41,56.82 37.23,56.82 37.74,56.31 40.03,56.31 41.73,58.02 44.29,58.02 44.7,58.42 44.7,59.41 44.55,59.56 44.22,59.56 44.08,59.42 44.08,59.2 v4(44.26,59.03)
MUX_SSRXN1_C: length 7.4
  TOP w0.053: D26102.2 44.16,62.77 ; 44.16,62.77 43.92,63.01 43.92,63.54 43.52,63.94 42.19,63.94 42.06,64.07 40.35,64.07 39.9,63.62 39.9,63.04 39.72,62.86 JUSB1.B10 ; 44.16,62.77 44.13,62.77 43.92,62.56 43.92,62.47 44.18,62.21 44.25,62.21 C2629.1
MUX_SSRXN2: length 6.6
  TOP w0.053: C2627.1 32.44,58.47 32.94,58.47 33.24,58.17 33.24,57.57 R2660.1 33.25,57.14 33.25,56.13 34.35,55.03 34.63,55.03 35.24,54.41 35.24,54.07 U3001.A3
MUX_SSRXN2_C: length 10.3
  TOP w0.053: JUSB1.A10 35.97,60.86 35.79,60.68 35.79,60.53 35.16,59.9 32.59,59.9 32.34,59.64 31.83,59.64 31.64,59.45 U2601.6 U2601.5 30.27,59.45 30.09,59.63 29.93,59.63 29.87,59.57 29.87,58.73 30.13,58.47 30.76,58.47 30.81,58.52 30.81,58.57 30.87,58.62 30.97,58.62 31.03,58.57 31.03,58.52 31.08,58.47 31.56,58.47 C2627.2
MUX_SSRXP1: length 20.3
  TOP w0.053: C2630.2 R2664.1 43.46,61.11 43.78,60.8 43.78,59.76 43.94,59.6 43.94,58.87 v3(43.82,58.75)
  S3 w0.051: v4(43.78,59.03) 43.76,59.01 43.76,58.81 v3(43.82,58.75) ; v4(35.43,56.03) 35.25,55.85 35.25,54.3 35.63,53.92 35.63,53.69 v3(35.77,53.54)
  S6 w0.051: v4(35.43,56.03) 35.25,56.21 35.25,56.49 35.46,56.7 37.18,56.7 37.69,56.19 40.08,56.19 41.78,57.89 44.35,57.89 44.82,58.37 44.82,59.46 44.6,59.68 44.17,59.68 43.96,59.47 43.96,59.21 v4(43.78,59.03)
MUX_SSRXP1_C: length 7.3
  TOP w0.053: C2630.1 43.51,62.21 43.78,62.48 43.78,62.59 43.58,62.79 43.54,62.79 ; 43.54,62.79 43.78,63.03 43.78,63.48 43.46,63.8 42.13,63.8 42.01,63.93 41.4,63.93 41.34,63.88 41.34,63.83 41.29,63.78 41.18,63.78 41.13,63.83 41.13,63.88 41.08,63.93 40.97,63.93 40.92,63.88 40.92,63.83 40.86,63.78 40.76,63.78 40.7,63.83 40.7,63.88 40.65,63.93 40.41,63.93 40.04,63.56 40.04,63.03 40.22,62.85 JUSB1.B11 ; 43.54,62.79 D26103.2
MUX_SSRXP2: length 6.6
  TOP w0.053: U3001.A2 35.1,54.07 35.1,54.36 34.98,54.48 34.9,54.48 34.87,54.46 34.8,54.46 34.72,54.53 34.72,54.61 34.75,54.63 34.75,54.71 34.57,54.89 34.29,54.89 33.11,56.07 33.11,57.1 R2661.1 33.1,57.59 33.1,58.11 32.88,58.34 32.44,58.34 C2628.1
MUX_SSRXP2_C: length 10.4
  TOP w0.053: C2628.2 31.57,58.33 30.07,58.33 29.73,58.67 29.73,59.63 29.87,59.77 30.07,59.77 30.25,59.95 U2601.4 U2601.7 31.64,59.95 31.81,59.78 32.28,59.78 32.53,60.03 35.1,60.03 35.65,60.59 35.65,60.69 35.47,60.87 JUSB1.A11
MUX_SSTXN1: length 11.5
  TOP w0.053: v3(36.21,54.57) 36.3,54.48 36.3,54.07 U3001.A5
  S3 w0.051: v3(42.46,57.69) 42.67,57.48 42.67,56.97 42.85,56.79 43.19,56.79 v4(43.38,56.6) ; v3(36.21,54.57) 36.21,54.8 v4(36.15,54.86)
  S6 w0.051: v4(36.15,54.86) 36.32,54.69 36.32,54.36 36.46,54.23 37.87,54.23 39.3,55.65 40.24,55.65 41.37,56.78 43.2,56.78 v4(43.38,56.6)
MUX_SSTXN1_C: length 6.1
  TOP w0.053: C2602.1 42.64,58.38 42.64,58.95 D26105.2 42.65,59.32 42.65,60.14 42.49,60.3 39.83,60.3 39.65,60.48 39.65,60.68 39.47,60.86 JUSB1.A3
MUX_SSTXN2: length 19.7
  S3 w0.051: v3(36.57,53.54) 36.44,53.68 36.44,53.73 36.65,53.94 37.62,53.94 38.46,54.78 38.46,57.77 v4(38.63,57.94) ; v4(28.92,57.05) 29.11,57.24 29.11,58.61 28.87,58.85 28.87,59.4 v3(28.65,59.62)
  S6 w0.051: v4(28.92,57.05) 29.11,57.23 29.11,57.37 29.33,57.59 32.05,57.59 32.44,57.98 35.84,57.98 36.56,58.7 38.1,58.7 38.45,58.35 38.45,58.12 v4(38.63,57.94)
MUX_SSTXN2_C: length 11.8
  TOP w0.053: C2603.1 28.89,60.36 28.89,60.94 29.22,61.27 30.07,61.27 30.25,61.45 U2601.1 U2601.10 31.64,61.45 31.82,61.27 32.06,61.27 32.2,61.41 32.2,63 33.22,64.01 35.69,64.01 36.04,63.66 36.04,63.07 36.22,62.89 JUSB1.B3
MUX_SSTXP1: length 11.4
  TOP w0.053: U3001.A6 36.44,54.07 36.44,54.48 v3(36.54,54.57)
  S3 w0.051: v3(42.99,57.69) 42.79,57.48 42.79,57.02 42.9,56.91 43.21,56.91 v4(43.38,57.08) ; v4(36.63,54.86) 36.54,54.77 v3(36.54,54.57)
  S6 w0.051: v4(36.63,54.86) 36.45,54.68 36.45,54.41 36.51,54.35 36.76,54.35 36.81,54.4 36.81,54.43 36.87,54.48 36.97,54.48 37.02,54.43 37.02,54.4 37.07,54.35 37.17,54.35 37.22,54.4 37.22,54.43 37.27,54.48 37.37,54.48 37.42,54.43 37.42,54.4 37.48,54.35 37.82,54.35 39.25,55.77 40.19,55.77 41.32,56.9 43.2,56.9 v4(43.38,57.08)
MUX_SSTXP1_C: length 6.1
  TOP w0.053: C2601.1 42.78,58.41 42.78,58.95 D26104.2 42.79,59.3 42.79,60.2 42.55,60.44 39.89,60.44 39.79,60.53 39.79,60.67 39.97,60.85 JUSB1.A2
MUX_SSTXP2: length 19.6
  S3 w0.051: v3(29.2,59.62) 28.99,59.41 28.99,58.9 29.23,58.66 29.23,57.22 v4(29.4,57.05) ; v4(38.15,57.94) 38.33,57.76 38.33,54.83 37.93,54.42 37.85,54.42 37.82,54.45 37.75,54.45 37.68,54.38 37.68,54.3 37.71,54.27 37.71,54.2 37.57,54.07 37.26,54.07 37.21,54.12 37.21,54.15 37.16,54.2 37.06,54.2 37.01,54.15 37.01,54.12 36.96,54.07 36.6,54.07 36.32,53.78 36.32,53.69 v3(36.17,53.54)
  S6 w0.051: v4(38.15,57.94) 38.33,58.11 38.33,58.3 38.05,58.58 36.61,58.58 35.89,57.86 32.49,57.86 32.1,57.47 29.38,57.47 29.23,57.32 29.23,57.22 v4(29.4,57.05)
MUX_SSTXP2_C: length 11.7
  TOP w0.053: JUSB1.B2 35.72,62.9 35.9,63.08 35.9,63.6 35.63,63.87 35.45,63.87 35.4,63.82 35.4,63.77 35.34,63.72 35.24,63.72 35.18,63.77 35.18,63.82 35.13,63.87 35.02,63.87 34.97,63.82 34.97,63.77 34.92,63.72 34.81,63.72 34.76,63.77 34.76,63.82 34.7,63.87 33.27,63.87 32.34,62.94 32.34,61.35 32.12,61.13 31.8,61.13 31.62,60.95 U2601.9 U2601.2 30.25,60.95 30.07,61.13 29.28,61.13 29.03,60.88 29.03,60.29 C2604.1
MUX_XTAL_IN: length 6.4
  TOP w0.066: Y3001.1 29.05,52.93 29.87,53.75 31.94,53.75 32.19,53.49 C3021.1 32.56,53.54 R3007.2 33.39,53.54 34.19,52.74 34.57,52.74 U3001.D1
MUX_XTAL_OUT: length 4
  TOP w0.066: Y3001.3 31.6,54.08 C3022.1 32.54,54.05 R3007.1 33.17,54.05 34.08,53.14 34.57,53.14 U3001.C1
OSC_16M_IN: length 4.1
  BOTTOM w0.066: Y2501.1 10.39,17.41 10.39,18.89 C2522.1 10.62,19.21 10.62,19.79 R2509.2
OSC_16M_OUT: length 2.1
  BOTTOM w0.066: R2511.2 10.06,19.81 C2523.1 10.06,18.84 Y2501.3
OSC_32K_IN: length 4.7
  BOTTOM w0.066: R2514.1 14.07,19.15 C2528.1 R2512.2 15.67,18.54 16.36,17.85 Y2502.2
OSC_32K_OUT: length 2.8
  BOTTOM w0.066: R2513.2 13.49,19.15 C2527.1 13.51,18.57 R2512.1 13.56,18.52 Y2502.1
PACK_VSNS_M: length 7.8
  TOP w0.066: v3(46.28,16.84) 46.29,16.85 R604.1
  S3 w0.064: v3(46.28,16.84) 46.28,16.74 46.35,16.67 46.58,16.67 46.76,16.49 46.76,16.15 46.61,16 45.2,16 43.87,14.67 40.78,14.67 v3(40.68,14.58)
PHONE_ON_N: length 78.3
  TOP w0.066: JBTN1.1 47.15,58.17 47.52,57.8 D26009.2 47.54,57.17 C2605.1 48.05,56.88 v3(48.84,56.08) ; JBTN1.1 47.2,58.54 48.39,59.73 49.94,59.73 v6(50.11,59.9) ; JBTN1.1 JBTN1.2
  S3 w0.064: v3(48.84,56.08) 48.84,55.04 48.71,54.9 48.71,51.71 49.24,51.18 49.24,21.6 48.44,20.8 48.44,9.71 v4(47.47,8.74) ; v4(38.58,14.74) 38.19,15.13 v3(37.28,15.13)
  S6 w0.064: v4(38.58,14.74) 38.58,14.22 40.82,11.98 40.82,11.02 41.97,9.87 43.01,9.87 43.54,9.35 46.86,9.35 v4(47.47,8.74)
  BOTTOM w0.066: TP2614.1 49.37,59.83 49.44,59.9 v6(50.11,59.9)
PM_AVDD_BYP: length 4.7
  S3 w0.064: v3(35.58,16.26) 35.48,16.36 35.24,16.36 34.89,16.01 34.6,16.01 33.54,14.95 33.04,14.95 32.77,14.68 32.76,14.68 32.74,14.66 32.1,14.66 31.8,14.96 31.8,14.95 v3(31.78,14.95)
PM_DVDD_BYP: length 5
  S3 w0.064: v3(35.86,15.98) 35.6,15.98 35.51,16.07 35.51,16.07 35.4,16.18 35.23,16.18 34.92,15.87 34.79,15.87 33.63,14.71 33.63,14.52 33.43,14.32 33.1,14.32 33.04,14.38 32.74,14.38 32.62,14.5 v3(31.85,14.5)
PM_REF_BYP: length 5.3
  TOP w0.066: C716.1 v3(31.64,13.51)
  S3 w0.06: 31.64,13.51 v3(31.64,13.51)
  S3 w0.064: 31.64,13.51 31.88,13.51 32.03,13.36 32.84,13.36 32.85,13.37 33.27,13.37 33.57,13.67 33.57,14.07 34.63,15.13 34.63,15.28 34.95,15.6 35.48,15.6 v3(35.58,15.7)
PM_RESIN_N: length 93.8
  TOP w0.066: PMIC1.N9 v3(36.52,15.41) ; JCTL1.8 43.25,52.62 43.49,52.38 v3(43.49,50.82) ; v3(41.17,42.96) 39.49,42.96 39.36,43.09 D26008.2 39.36,43.3 v3(38.86,43.3)
  S3 w0.064: v3(36.52,15.41) v4(36.25,15.41) ; v4(38.84,42.34) 38.86,42.36 v3(38.86,43.3) ; v3(43.49,50.82) 43.49,50.64 42.34,49.49 42.34,46.02 42.72,45.64 42.72,44.18 41.5,42.96 v3(41.17,42.96)
  S6 w0.064: v4(38.84,42.34) 38.81,42.34 38.73,42.42 37.41,42.42 36.6,41.61 34.72,41.61 33.32,40.21 22.45,40.21 20.29,38.05 20.29,13.78 24.31,9.76 24.31,8.61 24.64,8.28 35.56,8.28 35.88,8.6 38.72,8.6 39.85,9.73 39.85,11.68 38.87,12.66 38.86,12.66 38.56,12.96 38.56,12.98 37.71,13.83 37.71,15.98 37.56,16.13 36.1,16.13 35.89,15.93 35.89,15.6 36.07,15.41 v4(36.25,15.41)
PM_XTAL_IN: length 4.9
  TOP w0.066: Y701.3 33.51,10.16 C702.1 34.16,10.58 34.01,10.73 34.01,12.18 34.91,13.08 35.09,13.08 35.3,13.29 35.3,13.72 PMIC1.W5
PM_XTAL_OUT: length 4.8
  TOP w0.066: PMIC1.Y4 34.9,13.43 33.45,11.99 32.14,11.99 31.98,11.83 C701.1 32.63,11.4 Y701.1
PMIC_FORCED_USB_BOOT: length 4
  S3 w0.064: v3(34.77,21.95) 35.05,21.67 35.61,21.67 35.66,21.62 35.66,19.18 v3(35.29,18.81)
PMIC_PWM_TP: length 5.6
  S3 w0.064: v3(36.14,17.96) 36.14,22.29 v3(35.26,23.17)
PON_OPTION: length 4.5
  TOP w0.066: PMIC1.R9 v3(36.58,14.85)
  S3 w0.06: v3(36.58,14.85) 36.73,14.85 36.86,14.72 36.86,14.23 36.94,14.15 ; v3(36.4,10.99) 36.4,11.03
  S3 w0.064: 36.4,11.03 36.67,11.29 36.67,12.78 36.94,13.05 36.94,14.15
PS_HOLD: length 32.5
  TOP w0.066: R706.2 33.97,8.55 27.15,8.55 24.93,10.77 24.93,14.63 24.18,15.38 24.18,23.12 24.86,23.8 24.86,27.22 23.79,28.29 23.79,29.32 24.15,29.68 24.57,29.68 SOC1.AH27
PS_HOLD_R: length 7.1
  TOP w0.066: v3(35.89,9.96) 35.89,9.32 TP706.1 35.79,8.69 R709.1
  S3 w0.064: v3(35.89,9.96) 36.07,10.15 36.07,11.07 35.95,11.2 35.95,12.24 36.08,12.37 36.08,14.63 36.56,15.11 36.7,15.11 v3(36.73,15.14)
PWR_3P3V: length 192.8
  TOP w0.203: 13.67,6.58 13.85,6.39 QWIIC1.2 ; 13.67,6.58 R2613.1 ; 13.67,6.58 C2610.1 13.67,6.87 v3(13.64,6.9)
  TOP w0.254: U3004.1 27.6,60.82 v3(27.58,60.83) 28.73,61.98 R2735.1
  S3 w0.203: v3(27.58,60.83) 27.58,64.96 v4(27.2,65.35) ; v3(47.45,3.25) v3(45.55,3.25) v3(43.64,3.25) 43.63,3.25 43.62,3.26 v3(41.73,3.26) 41.37,3.26 v4(41.27,3.35) ; v3(16.01,6.56) 15.74,6.29 14.25,6.29 v3(13.64,6.9) 13.47,7.07 13.47,7.74 13.78,8.05 v4(14.35,8.05)
  V4 w0.203: v4(14.35,8.05) 14.72,8.42 23.83,8.42 25.16,9.75 31.52,9.75 37.92,3.35 v4(41.27,3.35) ; 2.54,37.05 JANALOG1.2 ; JANALOG1.2 3.59,38.1 ; JANALOG1.2 1.49,38.1 ; 2.54,31.97 JANALOG1.4 ; JANALOG1.4 1.49,33.02 ; JANALOG1.4 3.59,33.02 ; JANALOG1.4 2.54,34.07
  S6 w0.203: v5(32.38,11.86) v4(32.38,11.56) ; v1(10.9,27.61) 10.72,27.43 v4(10.64,27.43) ; v1(9.09,22.42) 9.12,22.42 9.35,22.2 v4(9.35,22.15) ; v1(13.31,29.57) 13.31,28.57 13.16,28.42 v1(13.16,27.76) ; v1(11.53,20.45) 11.4,20.32 v4(11.4,20.17) ; v1(7.65,27.36) v4(7.98,27.36) 8.65,27.36 v1(8.9,27.11) ; v4(7.69,25.15) v1(7.69,24.82) 7.9,24.61 v1(8.9,24.61) ; v1(18.9,14.94) v4(18.9,15.34) ; v1(18.97,36.61) 18.57,36.21 18.57,33.31 v1(18.96,32.92) ; v1(8.08,38.96) v4(7.52,38.96) ; v1(7.72,21.92) v4(7.44,21.92) ; 47.14,47.83 v1(47.24,47.73)
  S6 w1: v1(47.29,45.52) 47.14,45.67 47.14,60.51 46.53,61.12 44.31,61.12 43.21,60.02 41.3,60.02 40.48,60.84 36.11,60.84 34.85,59.59 32.33,59.59 31.76,60.15 31.76,62.42 28.67,65.51 27.47,65.51
  G7 w0.203: v1(9.9,22.11) 9.4,22.11 v1(9.09,22.42) ; v1(14.4,21.61) 14.58,21.79 14.58,22.29 v1(14.9,22.61) ; v5(32.38,11.86) 32.38,12.93 32.59,13.14 v1(33.28,13.14) 34.92,13.14 v1(35.32,13.54) ; 1.49,33.02 JANALOG1.4 ; JANALOG1.4 2.54,34.07 ; JANALOG1.4 3.59,33.02 ; JANALOG1.2 2.54,39.15 ; JANALOG1.2 2.54,37.05 ; JANALOG1.2 3.59,38.1 ; JANALOG1.2 1.49,38.1
  G7 w1: v1(9.29,60.83) 9.29,61.9 10.57,63.18 22.5,63.18 23.21,63.9 23.21,65.11 23.66,65.55 v5(25.39,65.55) v5(25.62,65.55)
  BOTTOM w0.203: C2508.1 v1(7.69,24.82) ; v1(11.53,20.45) C2506.1 11.9,20.46 MCU1.G1 ; v1(18.9,14.94) 18.41,15.42 18.41,20.73 17.88,21.26 C2505.1 C2503.1 16.36,21.26 15.01,22.61 v1(14.9,22.61) ; v1(18.97,36.61) 18.78,36.8 C1102.1 17.91,37.32 U1101.11 ; U2501.4 44.06,45.23 44.48,45.66 ; MCU1.D13 13.25,27.76 v1(13.16,27.76) 13.05,27.76 MCU1.E13 ; U2501.5 44.71,45.43 44.48,45.66 ; 16.79,27.23 16.79,28.92 15.98,29.73 ; 16.79,27.23 17.55,27.23 18.01,26.77 18.01,25.58 17.81,25.37 C2513.1 C2504.1 15.7,25.37 15.43,25.11 MCU1.A8 ; 16.79,27.23 16.43,26.87 C2509.1 15.62,26.87 15.36,26.61 MCU1.A11 ; 44.48,45.66 C2529.1 45.46,45.89 R2643.1 46.91,45.9 v1(47.29,45.52) ; v1(18.96,32.92) 18.16,32.92 17.94,32.7 16.48,32.7 16.15,32.37 16.15,31.48 U1102.6 ; C2518.1 v1(7.72,21.92) 7.98,21.92 8.67,22.61 MCU1.N3 v1(9.09,22.42) ; R2642.1 46.99,47.47 v1(47.24,47.73) ; C2616.1 6.81,38.25 ; R2666.1 v1(33.28,13.14)
  BOTTOM w0.524: JANALOG1.4 1.02,34.54 1.02,36.58 JANALOG1.2
  vias: v1(8.76,61.22) v1(8.76,60.83) v1(8.88,61.01) v1(8.9,60.65) v1(9.03,60.84) v1(9.15,61.01) v1(9.16,60.65) v1(9.42,60.65) v1(9.56,60.83) v1(9.7,60.65) v1(10.63,4.97) v1(10.82,4.81) v1(10.96,4.98) v1(11.15,4.82) v1(11.31,4.98) v1(11.5,4.82) v1(11.65,4.98) v1(11.84,4.82) v1(11.99,4.98) v1(12.18,4.82) v1(13.23,30.05) v1(13.16,29.82) v1(13.41,29.79) v4(9.04,61.28) v4(9.4,61.45) v4(9.43,61.09) v4(9.76,61.48) v4(9.81,61.12) v4(10.91,4.46) v4(11.11,4.13) v4(11.33,4.46) v4(11.53,4.12) v4(11.75,4.46) v4(11.98,4.13) v4(12.19,4.45) v4(12.88,30.02) v4(12.95,29.59) v4(13.33,20.55) v4(13.31,20.12) v4(26.42,65.73) v4(26.79,65.74) v4(26.81,65.36) v4(27.21,65.72) v5(8.76,61.22) v5(8.76,60.83) v5(8.88,61.01) v5(8.9,60.65) v5(9.03,60.84) v5(9.15,61.01) v5(9.16,60.65) v5(9.42,60.65) v5(9.56,60.83) v5(9.7,60.65) v5(10.63,4.97) v5(10.82,4.81) v5(10.96,4.98) v5(11.15,4.82) v5(11.31,4.98) v5(11.5,4.82) v5(11.65,4.98) v5(11.84,4.82) v5(11.99,4.98) v5(12.18,4.82) v5(13.23,30.05) v5(13.16,29.82) v5(13.41,29.79) v5(25.4,65.79) v5(25.39,65.32) v5(25.62,65.79) v5(25.62,65.32) v5(25.85,65.8) v5(25.85,65.56) v5(25.84,65.33) v5(26.08,65.8) v5(26.08,65.56) v5(26.07,65.33)
PWR_3P8V: length 17.7
  S6 w0.203: v1(15.56,42.43) 15.45,42.32 v4(15.29,42.32) ; v1(14.96,41.77) 14.79,41.61 v4(14.63,41.61) 11.22,41.61 v1(9.95,42.88) ; v4(13.16,36.93) 13.01,36.78 v1(12.73,36.78)
  BOTTOM w0.203: v1(9.65,31.84) 9.91,31.58 10.79,31.58 11.01,31.8 R2804.1 11.81,32.95 11.81,34.67 12.19,35.05 U2802.4 12.73,35.3 C2806.1 v1(12.73,36.78) ; R2802.1 13.34,39.5 C2803.1 14,39.5 14.99,40.49 14.99,41.74 v1(14.96,41.77)
  vias: v1(9.64,32.1) v1(9.95,43.34) v1(9.95,43.12) v1(9.88,32.12) v1(9.88,31.84) v1(12.71,36.56) v1(12.87,36.97) v1(12.92,36.62) v4(12.77,37.55) v4(13.04,37.27) v5(9.64,32.1) v5(9.95,43.34) v5(9.95,43.12) v5(9.88,32.12) v5(9.88,31.84) v5(12.71,36.56) v5(12.87,36.97) v5(12.92,36.62)
QCA_SB_CLK: length 45.3
  TOP w0.066: v3(9.97,60.42) 7.88,60.42 6.7,61.6 3.98,61.6 3.53,61.15 R2902.1
  S3 w0.064: v3(24.97,32.88) 21.57,36.28 17.77,36.28 17.23,36.82 14.43,36.82 11.52,39.73 11.52,45 9.68,46.84 9.68,49.54 10.16,50.03 10.16,60.23 v3(9.97,60.42)
QCA_SB_CLK_R: length 12.8
  TOP w0.066: R2902.2 4.03,61.25 4.21,61.43 6.61,61.43 7.86,60.18 10.12,60.18 11.43,61.49 13.95,61.49 U2901.6
QCA_SB_DATA: length 39.6
  S3 w0.064: v3(24.97,33.28) 24.85,33.28 21.64,36.49 17.86,36.49 17.34,37.01 14.52,37.01 11.7,39.83 11.7,45.2 9.93,46.96 9.93,49.35 10.56,49.98 v3(10.56,62.5)
QREFS_CXO_REXT: length 1.8
  TOP w0.066: SOC1.T30 29.37,28.27 29.41,28.23 R1601.1
QUIET_THERM: length 1.2
  S3 w0.064: v3(39.6,14.63) 39.59,14.64 39.59,14.97 v4(39.42,15.14)
  S6 w0.064: v4(39.42,15.14) 39.42,14.58 v1(39.47,14.53)
RESOUT_N: length 13.3
  TOP w0.066: v3(23.93,21.55) 23.93,23.11 24.66,23.84 24.66,27.18 23.64,28.2 23.64,29.55 SOC1.AJ26
  S3 w0.064: v4(26.36,22.45) 26.1,22.45 25.2,21.55 v3(23.93,21.55)
  S6 w0.066: v4(26.36,22.45) 26.87,22.45 v1(27.22,22.8)
RFCLK1_TP: length 3.2
  TOP w0.066: PMIC1.W1 33.2,12.75 31.86,12.75 31.74,12.87 TP701.1
RFCLK2: length 5.5
  S3 w0.064: v3(30.3,13.06) 30.68,13.06 31.3,12.44 32.62,12.44 32.63,12.43 33.65,12.43 34.25,13.03 34.25,13.18 34.25,13.18 34.25,13.8 v3(34.45,14)
RFCLK3_TP: length 8.1
  S3 w0.064: v3(29.34,11.66) 29.34,11.84 29.62,12.12 30.71,12.12 30.85,11.97 33.92,11.97 34.83,12.87 34.83,14.54 34.95,14.66 v3(35.02,14.66)
RTC_SLEEP_CLK: length 69.2
  TOP w0.066: R1204.1 5.6,49.18 R2903.1 5.01,49.19 v3(4.99,49.16)
  S3 w0.064: v3(36.71,17.39) 36.65,17.46 30.77,17.46 29.3,15.99 21.79,15.99 18.87,13.07 7.89,13.07 4.9,16.06 4.9,49.08 v3(4.99,49.16)
RTC_SLEEP_CLK_R: length 18.4
  TOP w0.066: v3(8.09,50.83) 6.95,49.69 R2903.2 ; v3(7.75,61.65) 7.92,61.82 10.98,61.82 U2901.9
  S3 w0.064: v3(8.09,50.83) 8.09,56.1 7.9,56.29 7.9,57.65 8.16,57.91 8.16,59.48 7.75,59.89 v3(7.75,61.65)
SBU1_AUXP: length 5.5
  TOP w0.051: v3(35.83,57.23) 35.7,57.36 35.7,57.5
  S3 w0.048: v3(34.93,53.54) 34.98,53.6 34.98,53.78 34.68,54.08 34.68,54.98 34.44,55.23 34.44,56.43 34.78,56.77 35.82,56.77 35.91,56.87 35.91,57.14 v3(35.83,57.23)
SBU2_AUXN: length 6
  TOP w0.051: v3(36.16,57.23) 36.24,57.31 36.24,57.5
  S3 w0.048: v3(36.16,57.23) 36.07,57.14 36.07,56.8 35.88,56.62 34.84,56.62 34.59,56.37 34.59,55.29 34.84,55.05 34.84,54.15 35.14,53.84 35.14,53.35 v3(34.93,53.14)
SD_CARD_DET_N_TP: length 2.2
  TOP w0.066: TP1315.1 22.85,36.56 23.01,36.72 24.34,36.72 24.57,36.49 SOC1.AH10
SDC1_CLK: length 19
  TOP w0.066: R1207.2 v3(36.25,26.55)
  S3 w0.079: v4(28.2,20.85) 28.55,21.2 29.25,21.2 29.57,21.52 30.65,21.52 30.73,21.44 30.73,20.82 30.81,20.74 30.97,20.74 31.04,20.81 31.04,21.44 31.12,21.52 31.28,21.52 31.36,21.44 31.36,20.82 31.44,20.74 31.6,20.74 31.67,20.81 31.67,21.44 31.75,21.52 31.91,21.52 31.99,21.44 31.99,20.82 32.07,20.74 32.23,20.74 32.3,20.81 32.3,21.44 32.38,21.52 32.54,21.52 32.62,21.44 32.62,20.83 32.69,20.75 32.85,20.75 32.93,20.84 32.93,21.28 36.4,24.75 36.4,26.4 v3(36.25,26.55)
  S6 w0.064: v1(28.22,22.3) 28.2,22.28 v4(28.2,20.85)
SDC1_CLK_TR: length 2.6
  TOP w0.066: SOC1.A29 35.37,28.88 35.7,28.55 35.7,27.5 35.35,27.15 35.35,26.55 R1207.1
SDC1_CMD: length 22
  S3 w0.064: 33.86,29.23 34.09,29.46 34.44,29.46 34.57,29.59 v3(34.57,29.68)
  S3 w0.079: 33.86,29.23 33.86,27.94 34.05,27.75 v4(34.05,25.6)
  S6 w0.079: v1(34.1,25.3) 34.1,25.6 v4(34.05,25.6)
  BOTTOM w0.084: EMMC1.M5 28.47,22.56 30.11,22.56 30.24,22.69 30.24,25.17 30.37,25.3 30.53,25.3 30.62,25.21 30.62,24.22 30.7,24.14 30.87,24.14 30.95,24.22 30.95,25.21 31.04,25.3 31.2,25.3 31.29,25.21 31.29,24.22 31.37,24.14 31.54,24.14 31.62,24.22 31.62,25.21 31.71,25.3 31.87,25.3 31.96,25.21 31.96,24.22 32.04,24.14 32.21,24.14 32.29,24.22 32.29,25.21 32.38,25.3 32.54,25.3 32.63,25.21 32.63,24.22 32.71,24.14 32.88,24.14 32.96,24.22 32.96,25.21 33.05,25.3 R2114.2
SDC1_DATA_0: length 22.5
  S3 w0.064: v3(34.97,29.28) 35.15,29.1 35.15,28.8 35.43,28.52 35.44,28.52
  S3 w0.079: v4(26.83,20.73) 27.53,20.73 28.2,21.4 29.15,21.4 29.45,21.7 32.77,21.7 35.75,24.68 35.75,28.21 35.44,28.52
  S6 w0.079: v4(26.83,20.73) 26.59,20.49 24.16,20.49 22.4,22.25 22.4,23.39 v1(22.82,23.82)
SDC1_DATA_1: length 21.2
  S3 w0.079: v3(34.97,28.88) 34.97,28.75 35.55,28.17 35.55,24.75 32.68,21.89 29.34,21.89 29.05,21.6 28.05,21.6 27.5,21.05 v4(26.42,21.05)
  S6 w0.079: v1(22.82,23.31) 22.6,23.09 22.6,22.4 24.33,20.67 24.55,20.67 24.63,20.75 24.63,20.79 24.71,20.87 24.87,20.87 24.95,20.79 24.95,20.75 25.02,20.67 25.18,20.67 25.26,20.75 25.26,20.79 25.34,20.87 25.5,20.87 25.58,20.79 25.58,20.75 25.65,20.67 26.03,20.67 v4(26.42,21.05)
SDC1_DATA_2: length 20.9
  S3 w0.079: v4(25.93,21.07) 25.93,21.25 26.05,21.37 27.53,21.37 27.96,21.8 29,21.8 29.25,22.05 32.55,22.05 35.35,24.85 35.35,28 34.97,28.38 v3(34.97,28.48)
  S6 w0.079: v4(25.93,21.07) 25.52,21.07 25.44,21.15 25.44,21.27 25.36,21.35 25.2,21.35 25.12,21.27 25.12,21.15 25.04,21.07 24.89,21.07 24.81,21.15 24.81,21.27 24.73,21.35 24.57,21.35 24.49,21.27 24.49,21.15 24.42,21.07 24.28,21.07 24.18,21.17 24.18,21.28 24.36,21.46 24.36,21.57 24.25,21.68 24.14,21.68 23.96,21.5 23.85,21.5 23.74,21.61 23.74,21.72 23.92,21.9 23.92,22.01 23.81,22.12 23.7,22.12 23.52,21.94 23.41,21.94 22.82,22.53 v1(22.82,22.8)
SDC1_DATA_3: length 21.8
  S3 w0.064: v3(34.57,29.28) 34.76,29.09
  S3 w0.079: v4(27.44,21.72) 27.72,22 28.9,22 29.12,22.23 29.42,22.23 29.5,22.3 29.5,22.42 29.58,22.5 29.74,22.5 29.81,22.42 29.81,22.3 29.89,22.23 30.05,22.23 30.13,22.3 30.13,22.42 30.21,22.5 30.36,22.5 30.44,22.42 30.44,22.3 30.52,22.23 32.43,22.23 35.15,24.95 35.15,27.95 34.76,28.34 34.76,29.09
  S6 w0.079: v1(23.22,24.3) 23.54,23.98 24.01,23.98 24.91,24.88 26.69,24.88 27.44,24.13 v4(27.44,21.72)
SDC1_DATA_4: length 21.7
  S3 w0.079: v3(34.57,28.88) 34.36,28.67 34.36,28.24 34.75,27.85 34.75,25.05 32.85,23.15 30.32,23.15 30.24,23.07 30.24,22.95 30.17,22.87 30.01,22.87 29.93,22.95 29.93,23.07 29.85,23.15 29.55,23.15 28.8,22.4 27.24,22.4 v4(26.54,21.7)
  S6 w0.079: v4(26.54,21.7) 26.45,21.7 26.03,22.12 26.03,22.71 26.37,23.05 26.72,23.05 26.94,23.27 26.94,24.12 26.62,24.45 24.98,24.45 24.08,23.55 23.47,23.55 v1(23.22,23.8)
SDC1_DATA_5: length 22.3
  S3 w0.064: v3(34.57,28.48) 34.57,28.29
  S3 w0.079: v4(26.99,21.72) 27.47,22.2 28.85,22.2 29.31,22.66 30.67,22.66 30.75,22.74 30.75,22.88 30.83,22.95 30.99,22.95 31.07,22.88 31.07,22.74 31.15,22.66 31.3,22.66 31.38,22.74 31.38,22.88 31.46,22.95 31.62,22.95 31.7,22.88 31.7,22.74 31.78,22.66 31.93,22.66 32.01,22.74 32.01,22.88 32.09,22.95 32.25,22.95 32.33,22.88 32.33,22.74 32.4,22.66 32.61,22.66 34.95,25 34.95,27.91 34.57,28.29
  S6 w0.079: v4(26.99,21.72) 26.64,21.37 26.43,21.37 25.81,21.99 25.81,22.82 26.31,23.32 26.6,23.32 26.72,23.44 26.72,24.03 26.51,24.24 25.11,24.24 24.17,23.3 v1(23.22,23.3)
SDC1_DATA_6: length 21.3
  S3 w0.064: 34.03,28.63 33.99,28.68 33.99,28.81 33.98,28.81 33.98,28.96 33.99,28.96 33.99,29.1 v3(34.17,29.28)
  S3 w0.079: v4(25.15,22.15) 25.8,22.8 28.65,22.8 29.4,23.55 32.7,23.55 34.35,25.2 34.35,27.7 34.03,28.02 34.03,28.63
  S6 w0.079: v1(23.22,22.8) 23.28,22.86 24.12,22.86 25.26,24 26.44,24 26.51,23.93 26.51,23.62 26.44,23.55 25.84,23.55 25.75,23.46 25.75,23.28 25.15,22.68 v4(25.15,22.15)
SDC1_DATA_7: length 21
  S3 w0.064: 34.38,24.97 34.39,24.97
  S3 w0.079: v3(34.17,28.88) 34.2,28.85 34.2,28.12 34.55,27.77 34.55,25.13 34.39,24.97 ; 34.38,24.97 32.77,23.35 29.5,23.35 28.75,22.6 26.9,22.6 25.85,21.55 v4(25.7,21.55)
  S6 w0.079: v1(23.32,22.38) 23.32,22.53 23.4,22.61 23.63,22.61 23.84,22.4 23.95,22.4 25.17,23.62 25.28,23.62 25.39,23.51 25.39,23.39 24.18,22.18 24.18,22.07 24.53,21.71 25.54,21.71 v4(25.7,21.55)
  BOTTOM w0.084: EMMC1.B6 23.24,22.3 v1(23.32,22.38)
SDC1_RCLK: length 20.6
  S3 w0.079: v4(36.1,24.9) 36,24.9 36,28.25 35.56,28.69 35.56,29.09 v3(35.37,29.28)
  S6 w0.064: v1(34.5,24.75) 34.5,24.75 35.85,24.75
  S6 w0.079: v4(36.1,24.9) 36,24.9 35.85,24.75
  BOTTOM w0.084: EMMC1.H5 26.52,23.1 27.4,23.1 27.7,22.8 27.7,22.2 27.85,22.05 30.22,22.05 30.61,22.44 30.73,22.44 31.08,22.1 31.2,22.1 31.31,22.22 31.31,22.33 30.97,22.68 30.97,22.8 31.09,22.92 31.2,22.92 31.55,22.57 31.67,22.57 31.79,22.69 31.79,22.81 31.44,23.16 31.44,23.27 31.69,23.53 32.33,23.53 32.43,23.43 32.43,22.88 32.51,22.79 32.68,22.79 32.76,22.88 32.76,23.42 32.87,23.53 33.1,23.53 33.47,23.89 33.47,24.61 33.61,24.75 R2113.1 34.5,24.75 v1(34.5,24.75)
SLEEP_CLK: length 31.8
  TOP w0.066: v3(9.19,49) 9.01,49.18 R1204.2
  G2 w0.066: v3(23.76,30.73) 23.97,30.52 24.41,30.52 24.57,30.36 v2(24.57,30.08)
  S3 w0.064: v3(23.76,30.73) 22.72,30.73 19.27,34.18 14.15,34.18 12.22,36.1 12.22,38.38 11.13,39.47 11.13,44.66 9.19,46.6 v3(9.19,49)
